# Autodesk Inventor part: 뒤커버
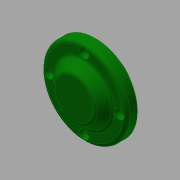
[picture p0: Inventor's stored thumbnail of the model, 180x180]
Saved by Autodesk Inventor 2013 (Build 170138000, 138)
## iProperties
Created: 2017-08
Part Number: 뒤커버
Material: 알루미늄 6061
Document SubType Name: Modeling
Designer: mduedu
Density: 1 g/cm^3
Author: mduedu
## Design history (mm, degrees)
sketch "스케치1"
  geometry: C1 r 35 at (0, 0); 1 further point
  constraints: 1 centre point, 1 coincident
  dimensions: "d0" = 70 diameter of C1
extrude "돌출1" new body sketch "스케치1" distance "d1" = 10; taper "d2" = 0 deg
sketch "스케치2"
  geometry: C1 r 24 at (0, 0); 1 further point
  constraints: 1 centre point, 1 coincident
  dimensions: "d3" = 48 diameter of C1
node "작업 평면1"
sketch "스케치3"
  geometry: C1 r 17 at (0, 0); 1 further point
  constraints: 1 centre point, 1 coincident
  dimensions: "d5" = 34 diameter of C1
feature "로프트1" sketch "스케치3" dims "d6" = 0, "d7" = 90 deg, "d8" = 0, "d9" = 90 deg
sketch "스케치4"
  geometry: C1 r 24 at (0, 0) reference; 1 further point
extrude "돌출2" join sketch "스케치4" distance "d10" = 8; taper "d11" = 0 deg
hole "구멍1" diameter "d14" = 40; stored, may be unused: countersink angle "d18" = 90 deg, drill point angle "d20" = 0 deg; dims "d12" = 10, "d13" = 10, "d15" = 6, "d16" = 4, "d17" = 2, "d19" = 12
hole "구멍2" diameter "d23" = 34; stored, may be unused: countersink angle "d27" = 90 deg, drill point angle "d29" = 0 deg; dims "d24" = 6, "d25" = 4, "d26" = 2, "d28" = 6, "d62" = 10, "d63" = 10
chamfer "모따기1" distance "d39" = 1; stored, may be unused: second distance "d40" = 2, angle "d41" = 45 deg
fillet "모깎기1" dims "d42" = 0.3
fillet "모깎기2" dims "d43" = 3
sketch "스케치5" dims "d44" = 58
  geometry: 6 further points
  constraints: 2 vertical alignment, 1 coincident, 7 other
  dimensions: "d47" = 360 deg dimension on point (0, 0) point (0, 29) (derived)
sketch "스케치6"
  geometry: 4 further points
  constraints: 4 other
hole "구멍4" sketch "스케치6" at (0, 29), (-29, 0), (29, 0), (0, -29) diameter "d49" = 4.5; stored, may be unused: countersink angle "d53" = 90 deg, drill point angle "d55" = 0 deg; dims "d50" = 6, "d51" = 8, "d52" = 4.6, "d54" = 8
fillet "모깎기3" dims "d56" = 3
fillet "모깎기4" dims "d57" = 3
fillet "모깎기5" dims "d58" = 3
chamfer "모따기2" distance "d59" = 1; stored, may be unused: second distance "d60" = 2, angle "d61" = 45 deg
node "솔리드1"
other parameters: "d4" = 8
